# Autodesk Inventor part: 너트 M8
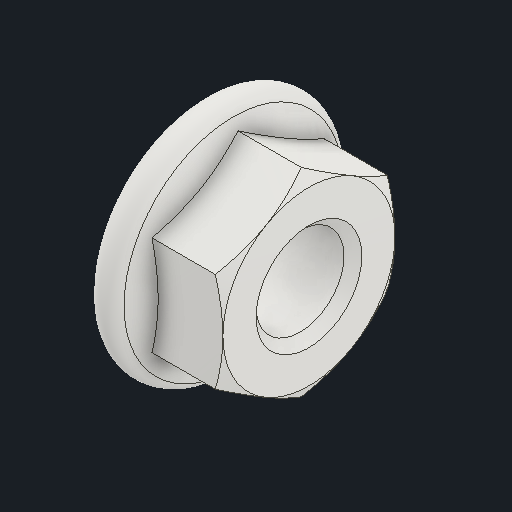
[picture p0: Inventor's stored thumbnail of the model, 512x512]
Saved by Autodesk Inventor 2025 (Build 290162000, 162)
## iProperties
Created: 2025-08
Part Number: 너트 M8
Material: 스테인리스강
Description: 플랜지붙이 6각 너트 - 일반 스레드
Document SubType Name: Modeling
Designer: infra15
Density: 8 g/cm^3
Appearance: 기본값
Author: jhkim
Sending System: Autodesk Inventor 2026
Preprocessor: ST-DEVELOPER v20.1
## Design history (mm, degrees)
feature "Solid1"
node "솔리드1"
